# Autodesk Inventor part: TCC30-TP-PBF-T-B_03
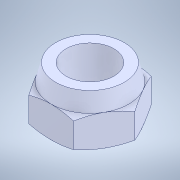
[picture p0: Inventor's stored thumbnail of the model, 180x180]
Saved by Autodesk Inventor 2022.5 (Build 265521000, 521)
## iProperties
Created: 2023-09
Part Number: TCC30-TP-PBF-T-B_03
Material: 一般
Document SubType Name: Modeling
Designer: ImaoCorp
Density: 1 g/cm^3
Appearance: 既定
Author: ImaoCorp
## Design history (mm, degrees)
feature "TCC30-TP-PBF-T-B_03"
node "ソリッド1"
